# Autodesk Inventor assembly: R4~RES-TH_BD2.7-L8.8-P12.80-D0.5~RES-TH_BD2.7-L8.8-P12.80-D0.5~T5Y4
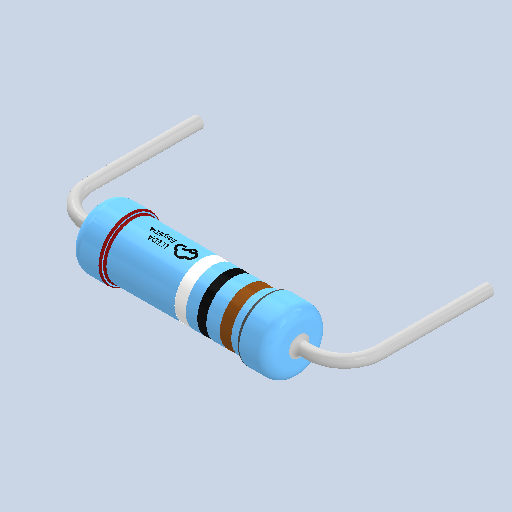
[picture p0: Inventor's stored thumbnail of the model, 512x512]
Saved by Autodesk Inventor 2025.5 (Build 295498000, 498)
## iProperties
Created: 2026-10
Part Number: R4~RES-TH_BD2.7-L8.8-P12.80-D0.5~RES-TH_BD2.7-L8.8-P12.80-D0.5~T5Y4
Document SubType Name: Assembly
Designer: Luis M
Author: Luis M
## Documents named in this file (2)
- C:\Users\Luis M\Downloads\3D_PCB1_2026-10-28\R4~RES-TH_BD2.7-L8.8-P12.80-D0.5~RES-TH_BD2.7-L8.8-P12.80-D0.5~T5Y4.iam
- C:\Users\Luis M\Downloads\3D_PCB1_2026-10-28\RES-TH_BD2.7-L8.8-P12.80-D0.5~RES-TH_BD2.7-L8.8-P12.80-D0.5~UAzC.ipt
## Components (1 placed, 1 different names)
1. R4->0
